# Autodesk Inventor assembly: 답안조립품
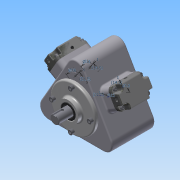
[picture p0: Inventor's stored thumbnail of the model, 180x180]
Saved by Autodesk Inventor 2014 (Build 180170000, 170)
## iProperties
Created: 2015-06
Part Number: 답안조립품
Document SubType Name: Assembly
Designer: Administrator
Mass: 5776.4 g
Surface Area: 2414.93 cm^2
Volume: 1564.62 cm^3
Density: 3.69189 g/cm^3
Author: Administrator
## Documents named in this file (20)
- C:\Documents and Settings\MYHOME\바탕 화면\350605V1053\답안조립품.iam
- C:\Documents and Settings\MYHOME\바탕 화면\350605V1053\본체.ipt
- C:\Documents and Settings\MYHOME\바탕 화면\350605V1053\부시.ipt
- C:\Documents and Settings\MYHOME\바탕 화면\350605V1053\편심축.ipt
- C:\Documents and Settings\MYHOME\바탕 화면\350605V1053\베어링 NA 4904.ipt
- 베어링 NA 4904.ipt
- C:\Documents and Settings\MYHOME\바탕 화면\350605V1053\슬라이드.ipt
- C:\Documents and Settings\MYHOME\바탕 화면\350605V1053\앞커버.ipt
- C:\Documents and Settings\MYHOME\바탕 화면\350605V1053\오일실.ipt
- 오일실.ipt
- C:\Documents and Settings\MYHOME\바탕 화면\350605V1053\헤더커버.ipt
- 헤더커버.ipt
- C:\Documents and Settings\MYHOME\바탕 화면\350605V1053\M6x0.7x20.ipt
- M6x0.7x20.ipt
- C:\Documents and Settings\MYHOME\바탕 화면\350605V1053\M4x0.5x16.ipt
- M4x0.5x16.ipt
- C:\Documents and Settings\MYHOME\바탕 화면\350605V1053\스프링2.ipt
- C:\Documents and Settings\MYHOME\바탕 화면\350605V1053\스프링1.ipt
- C:\Documents and Settings\MYHOME\바탕 화면\350605V1053\스프링4.ipt
- C:\Documents and Settings\MYHOME\바탕 화면\350605V1053\스프링3.ipt
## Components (14 placed, 3 different names)
1. 헤더커버:1
2. 헤더커버:2
3. M6x0.7x20:1
4. M6x0.7x20:2
5. M6x0.7x20:3
6. M6x0.7x20:4
7. M4x0.5x16:1
8. M4x0.5x16:2
9. M4x0.5x16:3
10. M4x0.5x16:4
11. M4x0.5x16:5
12. M4x0.5x16:6
13. M4x0.5x16:7
14. M4x0.5x16:8
